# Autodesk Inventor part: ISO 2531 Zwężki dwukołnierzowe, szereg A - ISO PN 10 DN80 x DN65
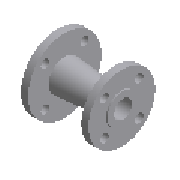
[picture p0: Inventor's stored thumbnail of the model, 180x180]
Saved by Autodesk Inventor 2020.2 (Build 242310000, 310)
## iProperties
IsCustomPart: 0
NAME: PIPING: ISO 2531 Double Flanged Taper PN 10 Series A
DATA: <meta><inlinegroups number="1" deflen="15"></inlinegroups><connections number="2"></connections><angles><a>3.14159265358979</a></angles></meta>
Manager: www.cadconsulting.pl
Company: Fabian Stasiak CAD Consulting
Created: 2014-02
Part Number: ISO 2531 Zwężki dwukołnierzowe, szereg A - ISO PN 10 DN80 x DN65
Material: Żeliwo sferoidalne
Description: Rury, łączniki, akcesoria z żeliwa sferoidalnego i ich złącza do zastosowań w instalacjach wodnych lub gazowych - Zwężki dwukołnierzowe, szereg A - ISO PN 10
Document SubType Name: Modeling
Standard: ISO 2531
Designer: F.Stasiak
Standard Revision: Fifth edition 1998-08-15
Standards Organization: ISO
Language: pl-PL
Size Designation: DN80 x DN65
Categories: <MemberInstance><Categories><Category DisplayName="Rury cienko- i grubościenne" InternalName="4347fa0f-2144-441d-94cd-e3e15c92b736" Mnemonic="TUBEANDPIPE"><Cate
Density: 7.15 g/cm^3
Appearance: Ciemnoszary
Catalog Web Link: www.expertbooks.pl
Author: F.Stasiak
Subject: Zbiór ćwiczeń. Autodesk Inventor 2020. Kurs Professional
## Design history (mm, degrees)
sketch "Sketch1"
  geometry: L1 (0, 0)-(200, 0); L2 (200, 0)-(200, 32.5); L3 (200, 52)-(197, 52); L4 (197, 52)-(197, 92.5); L5 (197, 92.5)-(181, 92.5); L6 (181, 92.5)-(181, 42.008); L7 (19, 52.833)-(19, 100); L8 (19, 100)-(3, 100); L9 (3, 100)-(3, 60); L10 (3, 60)-(0, 60); L11 (0, 60)-(0, 40); L12 (0, 40)-(0, 0); L13 (200, 52)-(200, 32.5); L14 (85.667, 47)-(152.333, 39.5); L15 (0, 40)-(66.667, 40); L16 (66.667, 40)-(133.333, 32.5); L17 (133.333, 32.5)-(200, 32.5); L18 (85.667, 47)-(19, 52.833); L19 (152.333, 39.5)-(181, 42.008); 1 further point
  constraints: 40 end point, 12 parallel, 2 horizontal, 2 perpendicular, 1 coincident
  dimensions: "d0" = 3 distance of L9.end L10.end; "d1" = 3 distance of L3.start L3.end; "d3" = 80 diameter of L11.end L1 (= d); "d4" = 65 diameter of L2.end L1 (= d2); "d5" = 120 diameter of L10 L1 (= N3); "d6" = 104 diameter of L3 L1 (= N32); "d7" = 200 diameter of L8 L1 (= D1); "d8" = 185 diameter of L5 L1 (= D2); "d9" = 200 distance of L1.start L1.end (= L); "d10" = 19 distance between parallel lines of L11 L7 (= C7); "d11" = 19 distance between parallel lines of L13 L6 (= C72); "d15" = 66.66667 distance of L11.end L15.end (= 0.333333 x L); "d16" = 66.66667 distance of L16.end L2.end (= 0.333333 x L); "d17" = 7 vertical distance of L14.start L15.end (= e1); "d18" = 7 distance from line of L14.end L17 (= e2); "d19" = 66.66667 horizontal distance of L14.start L7.start (= 0.333333 x L); "d20" = 5 deg angle of L15 L18; "d21" = 5 deg angle of L17 L19
revolve "Revolution1" sketch "Sketch1" stored, may be unused: angle "d14" = 90 deg
sketch "Sketch2"
  geometry: L1 (0, 0)-(0, 80); L2 (0, 0)-(30.615, 73.91); C1 r 9.5 at (30.615, 73.91); C2 r 40 at (0, 0) reference; A1 r 80 centre (0, 0) between (30.615, 73.91) and (0, 80)
  constraints: 4 end point, 2 centre point, 2 point on circle, 1 coincident, 1 vertical
  dimensions: "d23" = 19 diameter of C1 (= L2); "d24" = 160 diameter of A1 (= K1); "d25" = 22.5 deg angle of L1 L2 (computed from NU1)
extrude "Extrusion1" cut sketch "Sketch2" distance "d26" = 19 (= C7); taper "d27" = 0 deg
pattern_circular "Circular Pattern1" dims angle "d13" = 360 deg
sketch "Sketch3"
  geometry: L1 (0, 0)-(51.265, 51.265); L2 (0, 0)-(0, 72.5); C1 r 52 at (0, 0) reference; C2 r 9.5 at (51.265, 51.265); C3 r 52 at (0, 0) reference; A1 r 72.5 centre (0, 0) between (51.265, 51.265) and (0, 72.5)
  constraints: 4 end point, 2 centre point, 2 point on circle, 1 coincident, 1 vertical
  dimensions: "d28" = 45 deg angle of L2 L1 (computed from NU2); "d32" = 19 diameter of C2 (= L22); "d33" = 145 diameter of A1 (= K2)
extrude "Extrusion2" cut sketch "Sketch3" taper "d29" = 0 deg; stored distance "d46" = 19 (= C7)
pattern_circular "Circular Pattern2" dims angle "d31" = 360 deg
workaxis "Work Axis1"
workpoint "Work Point1"
workaxis "Work Axis2"
workpoint "Work Point2"
body "Solid1"
other parameters: "D1" = 200 [user parameter; used in 1 equation term], "C7" = 19 [user parameter; used in 3 equation terms], "e1" = 7 [user parameter; used in 1 equation term], "d" = 80 [user parameter; used in 1 equation term], "L" = 200 [user parameter; used in 4 equation terms], "N3" = 120 [user parameter; used in 1 equation term], "K1" = 160 [user parameter; used in 1 equation term], "L2" = 19 [user parameter; used in 1 equation term], "D2" = 185 [user parameter; used in 1 equation term], "C72" = 19 [user parameter; used in 1 equation term], "d2" = 65 [user parameter; used in 1 equation term], "N32" = 104 [user parameter; used in 1 equation term], "K2" = 145 [user parameter; used in 1 equation term], "L22" = 19 [user parameter; used in 1 equation term], "e2" = 7 [user parameter; used in 1 equation term], "Size_Designation" = 12.345 [user parameter]
